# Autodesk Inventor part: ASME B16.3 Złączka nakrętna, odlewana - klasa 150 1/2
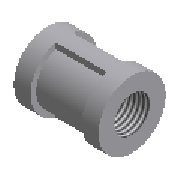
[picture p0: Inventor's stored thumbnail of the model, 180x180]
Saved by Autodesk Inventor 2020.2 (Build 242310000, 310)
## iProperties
Manager: www.cadconsulting.pl
Company: Fabian Stasiak CAD Consulting
IsCustomPart: 0
Created: 2014-02
Part Number: ASME B16.3 Złączka nakrętna, odlewana - klasa 150 1/2
Material: Żelazo, ciągliwe
Description: Złączka nakrętna
Document SubType Name: Modeling
Standard: ASME B16.3
Designer: F.Stasiak
Standard Revision: 1988
Standards Organization: ANSI
Language: pl-PL
Size Designation: 1/2
Categories: <MemberInstance><Categories><Category DisplayName="Rury cienko- i grubościenne" InternalName="4347fa0f-2144-441d-94cd-e3e15c92b736" Mnemonic="TUBEANDPIPE"><Cate
Density: 7.15 g/cm^3
Appearance: Częściowo polerowana
Catalog Web Link: www.expertbooks.pl
NAME: PIPING: ASME B16.3 Cast Coupling - Class 150
DATA: <meta><inlinegroups number="1" deflen="2.6924"></inlinegroups><connections number="2"></connections><angles><a>3.14159265358979</a></angles></meta>
Author: F.Stasiak
Subject: Zbiór ćwiczeń. Autodesk Inventor 2020. Kurs Professional
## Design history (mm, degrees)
sketch "Sketch1"
  geometry: L1 (0, 0)-(34.036, 0); L2 (34.036, 9.16)-(34.036, 15.24); L3 (34.036, 15.24)-(27.686, 15.24); L4 (27.686, 15.24)-(27.686, 13.123); L5 (27.686, 13.123)-(6.35, 13.123); L6 (6.35, 13.123)-(6.35, 15.24); L7 (6.35, 15.24)-(0, 15.24); L8 (23.114, 8.819)-(34.036, 9.16); L9 (34.036, 9.16)-(34.036, 0); L10 (17.018, 0)-(17.018, 13.123); L11 (0, 9.16)-(0, 15.24); L12 (0, 15.24)-(6.35, 15.24); L13 (6.35, 15.24)-(6.35, 13.123); L14 (10.922, 8.819)-(0, 9.16); L15 (0, 9.16)-(0, 0); L16 (10.922, 8.819)-(23.114, 8.819); L17 (10.922, 8.819)-(10.922, 0); L18 (23.114, 8.819)-(23.114, 0); 1 further point
  constraints: 36 end point, 6 perpendicular, 2 collinear, 2 midpoint, 2 parallel, 2 point on line, 2 symmetric about line, 1 coincident, 1 horizontal, 5 other
  dimensions: "d0" = 30.48 diameter of L7.end L1 (= H); "d1" = 6.35 distance of L3.end L2.end (= E1); "d2" = 18.32077 diameter of L2.start L1 (= MD); "d3" = 2.11667 distance of L3.end L4.end (= 0.333333 x E1); "d9" = 34.036 distance of L2.end L7.end (= W1); "d10" = 10.922 horizontal distance of L8.start L2.start (= B); "d13" = 1.78991 deg angle of L1 L8
revolve "Revolution1" sketch "Sketch1" stored, may be unused: angle "d8" = 90 deg
sketch "Sketch2"
  geometry: L1 (0, 15.24)-(0, 13.123); L2 (-3.404, 12.674)-(-3.404, 14.855); L3 (3.404, 12.674)-(3.404, 14.855); A1 r 15.24 centre (0, 0) between (3.404, 14.855) and (-3.404, 14.855); A2 r 13.123 centre (0, 0) between (3.404, 12.674) and (-3.404, 12.674); 3 further points
  constraints: 6 end point, 4 point on circle, 2 centre point, 2 vertical alignment, 1 coincident, 1 parallel, 1 symmetric about line, 1 vertical, 7 other
  dimensions: "d6" = 6.8072 diameter of L3 L1 (= 0.2 x W1)
extrude "Extrusion1" join sketch "Sketch2" taper "d7" = 0 deg; stored distance "d18" = 18.32077 (= MD)
mirror "Mirror1"
workpoint "Work Point1"
workpoint "Work Point2"
workaxis "Work Axis1"
workpoint "Work Point3"
workaxis "Work Axis2"
workpoint "Work Point4"
body "Solid1"
feature "Gwint1" dims "d4" = 10.922 (= B), "d5" = 0
feature "Gwint2" dims "d11" = 10.922 (= B), "d12" = 0
other parameters: "H" = 30.48 [user parameter; used in 1 equation term], "MD" = 18.32077 [user parameter; used in 2 equation terms], "W1" = 34.036 [user parameter; used in 2 equation terms], "E1" = 6.35 [user parameter; used in 2 equation terms], "B" = 10.922 [user parameter; used in 3 equation terms], "Size_Designation" = 5 [user parameter]
